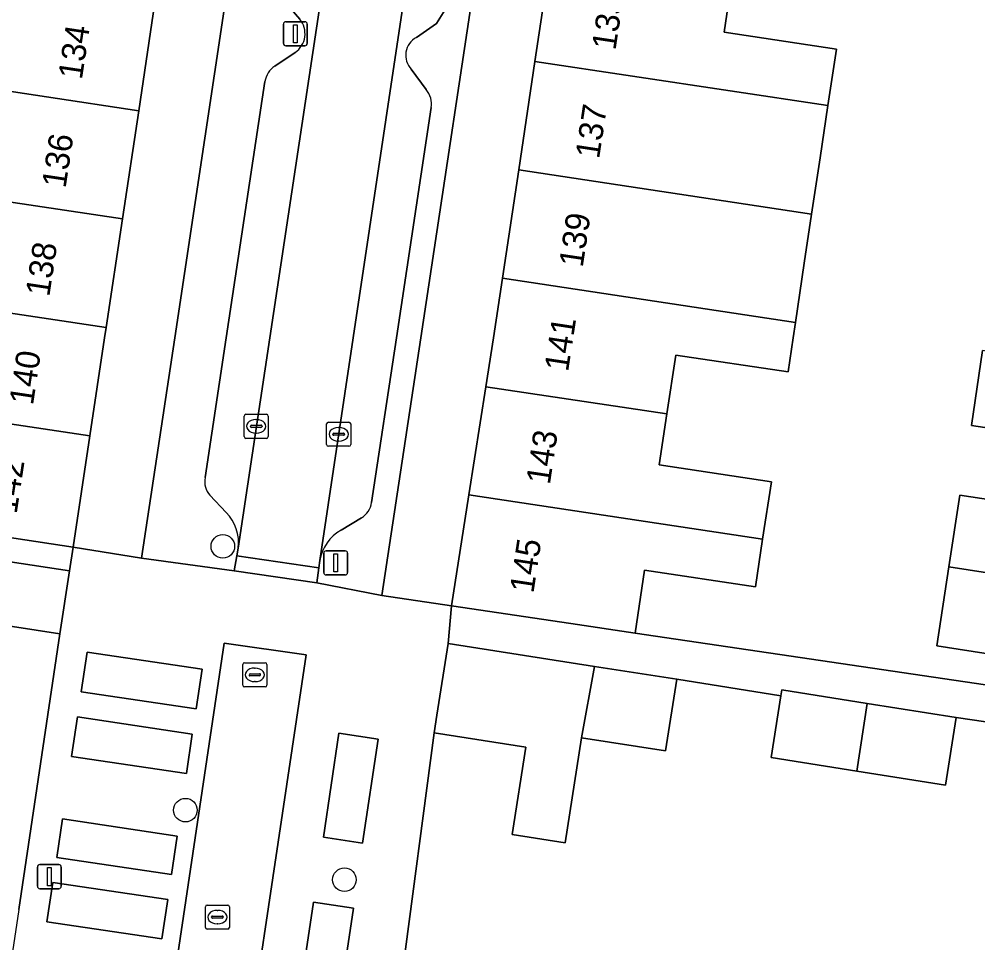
# Model space of a CAD drawing. Extents: x 163008 to 163854, y 382777 to 383982.
# Drawn here: x 163667.4 to 163707.17, y 383224.9 to 383263.21 of the extents above; entities that cross this region are included whole.
import ezdxf

# ---------------------------------------------------------------- set-up
doc = ezdxf.new("R2010")
doc.units = 0
for name, color, linetype in [('IMGEO_Boom', 7, 'Continuous'), ('IMGEO_Erf', 7, 'Continuous'), ('IMGEO_Kolk', 7, 'Continuous'), ('IMGEO_Lichtmast', 7, 'Continuous'), ('IMGEO_Muur', 7, 'Continuous'), ('IMGEO_Pand', 7, 'Continuous'), ('IMGEO_Pand_nummerreeks', 7, 'Continuous'), ('IMGEO_Parkeervlak_open', 7, 'Continuous'), ('IMGEO_Rijbaan_lokaal_open', 7, 'Continuous'), ('IMGEO_Voetpad_open', 7, 'Continuous')]:
    doc.layers.add(name, color=color, linetype=linetype)

msp = doc.modelspace()

# ---------------------------------------------------------------- linework, layer by layer
at = {"layer": 'IMGEO_Boom'}
for centre in [(163675.846, 383241.347), (163674.295, 383230.407), (163680.89, 383227.521)]:
    msp.add_circle(centre, 0.489, dxfattribs=at)
at = {"layer": 'IMGEO_Erf'}
for points in [[(163700.353, 383357.923), (163684.056, 383250), (163682.442, 383239.311), (163685.338, 383238.887), (163686.056, 383243.479), (163686.758, 383247.971), (163687.075, 383250), (163687.445, 383252.466), (163688.119, 383256.962), (163688.794, 383261.46), (163689.468, 383265.956)], [(163696.965, 383264.827), (163696.642, 383262.673), (163701.299, 383261.975), (163700.947, 383259.629), (163700.622, 383257.464), (163700.269, 383255.132), (163699.96, 383253.09), (163699.602, 383250.634), (163699.51, 383250), (163699.303, 383248.58), (163694.635, 383249.284), (163694.266, 383246.84), (163693.948, 383244.73), (163698.601, 383244.029), (163698.241, 383241.643), (163697.943, 383239.667), (163693.341, 383240.361), (163692.947, 383237.75), (163708.335, 383235.474)], [(163709.865, 383245.92), (163706.9, 383246.354), (163707.355, 383249.466)], [(163707.855, 383236.849), (163705.463, 383237.215), (163705.963, 383240.493), (163706.417, 383243.469), (163709.342, 383243.022)], [(163667.379, 383226.279), (163669.088, 383237.721), (163664.162, 383238.475)], [(163710.424, 383233.636), (163706.268, 383234.245), (163705.824, 383231.443), (163702.144, 383232.027), (163698.593, 383232.59), (163699, 383235.152), (163694.675, 383235.839), (163694.21, 383232.86), (163690.723, 383233.405), (163690.042, 383229.054), (163687.848, 383229.397), (163688.413, 383233.024), (163684.611, 383233.617), (163683.271, 383223.496)]]:
    msp.add_lwpolyline(points, dxfattribs=at)
msp.add_lwpolyline([(163681.279, 383299.422), (163678.43, 383299.85), (163677.757, 383295.368), (163677.082, 383290.874), (163676.407, 383286.381), (163675.732, 383281.887), (163675.057, 383277.393), (163674.382, 383272.9), (163673.707, 383268.406), (163673.032, 383263.912), (163672.357, 383259.419), (163671.682, 383254.926), (163671.007, 383250.432), (163670.942, 383250), (163670.331, 383245.933), (163669.638, 383241.316), (163672.477, 383240.858), (163673.851, 383250)], close=True, dxfattribs=at)
at = {"layer": 'IMGEO_Kolk'}
for p, q in [((163676.73, 383245.901), (163676.73, 383246.753)), ((163676.805, 383246.827), (163677.657, 383246.827)), ((163677.731, 383246.753), (163677.731, 383245.901)), ((163677.032, 383246.37), (163677.43, 383246.37)), ((163677.218, 383246.607), (163677.243, 383246.607)), ((163680.152, 383245.571), (163680.152, 383246.423)), ((163680.227, 383246.497), (163681.079, 383246.497)), ((163681.153, 383246.423), (163681.153, 383245.571)), ((163676.989, 383246.321), (163676.989, 383246.333)), ((163677.427, 383246.284), (163677.029, 383246.284)), ((163677.241, 383246.047), (163677.216, 383246.047)), ((163677.473, 383246.333), (163677.473, 383246.321)), ((163680.411, 383245.991), (163680.411, 383246.003)), ((163680.849, 383245.954), (163680.451, 383245.954)), ((163680.454, 383246.04), (163680.852, 383246.04)), ((163680.64, 383246.277), (163680.665, 383246.277)), ((163680.895, 383246.003), (163680.895, 383245.991)), ((163677.657, 383245.827), (163676.805, 383245.827)), ((163680.663, 383245.717), (163680.638, 383245.717)), ((163681.079, 383245.497), (163680.227, 383245.497)), ((163676.673, 383235.592), (163676.673, 383236.444)), ((163676.748, 383236.518), (163677.6, 383236.518)), ((163677.674, 383236.444), (163677.674, 383235.592)), ((163676.932, 383236.012), (163676.932, 383236.024)), ((163676.975, 383236.061), (163677.373, 383236.061)), ((163677.161, 383236.298), (163677.186, 383236.298)), ((163677.416, 383236.024), (163677.416, 383236.012)), ((163677.37, 383235.975), (163676.972, 383235.975)), ((163677.184, 383235.738), (163677.159, 383235.738)), ((163677.6, 383235.518), (163676.748, 383235.518)), ((163675.196, 383226.47), (163676.048, 383226.47)), ((163675.121, 383225.544), (163675.121, 383226.396)), ((163675.609, 383226.25), (163675.634, 383226.25)), ((163676.122, 383226.396), (163676.122, 383225.544)), ((163675.38, 383225.964), (163675.38, 383225.976)), ((163675.818, 383225.927), (163675.42, 383225.927)), ((163675.423, 383226.013), (163675.821, 383226.013)), ((163675.632, 383225.69), (163675.607, 383225.69)), ((163675.864, 383225.976), (163675.864, 383225.964)), ((163676.048, 383225.47), (163675.196, 383225.47))]:
    msp.add_line(p, q, dxfattribs=at)
for points in [[(163676.73, 383245.901), (163676.73, 383246.753)], [(163676.805, 383246.827), (163677.657, 383246.827)], [(163677.731, 383246.753), (163677.731, 383245.901)], [(163680.152, 383245.571), (163680.152, 383246.423)], [(163680.227, 383246.497), (163681.079, 383246.497)], [(163681.153, 383246.423), (163681.153, 383245.571)], [(163677.657, 383245.827), (163676.805, 383245.827)], [(163681.079, 383245.497), (163680.227, 383245.497)], [(163676.673, 383235.592), (163676.673, 383236.444)], [(163676.748, 383236.518), (163677.6, 383236.518)], [(163677.674, 383236.444), (163677.674, 383235.592)], [(163677.6, 383235.518), (163676.748, 383235.518)], [(163675.196, 383226.47), (163676.048, 383226.47)], [(163675.121, 383225.544), (163675.121, 383226.396)], [(163676.122, 383226.396), (163676.122, 383225.544)], [(163676.048, 383225.47), (163675.196, 383225.47)]]:
    msp.add_lwpolyline(points, dxfattribs=at)
for centre, radius, start, end in [((163676.807, 383246.751), 0.0765, 91.552, 178.448), ((163676.807, 383246.751), 0.0765, 91.552, 178.448), ((163677.655, 383246.751), 0.0765, 1.552, 88.448), ((163677.655, 383246.751), 0.0765, 1.552, 88.448), ((163677.029, 383246.33), 0.0403, 85.8775, 175.7526), ((163677.434, 383246.332), 0.0386, 1.7309, 96.639), ((163680.229, 383246.421), 0.0765, 91.552, 178.448), ((163680.229, 383246.421), 0.0765, 91.552, 178.448), ((163681.077, 383246.421), 0.0765, 1.552, 88.448), ((163681.077, 383246.421), 0.0765, 1.552, 88.448), ((163677.026, 383246.32), 0.0366, 178.938, 274.7102), ((163677.43, 383246.327), 0.043, 264.8664, 352.4533), ((163680.451, 383246), 0.0403, 85.8775, 175.7526), ((163680.448, 383245.99), 0.0366, 178.938, 274.7102), ((163680.852, 383245.997), 0.043, 264.8664, 352.4533), ((163680.856, 383246.002), 0.0386, 1.7309, 96.639), ((163676.807, 383245.903), 0.0765, 181.552, 268.448), ((163676.807, 383245.903), 0.0765, 181.552, 268.448), ((163677.655, 383245.903), 0.0765, 271.552, 358.448), ((163677.655, 383245.903), 0.0765, 271.552, 358.448), ((163680.229, 383245.573), 0.0765, 181.552, 268.448), ((163680.229, 383245.573), 0.0765, 181.552, 268.448), ((163681.077, 383245.573), 0.0765, 271.552, 358.448), ((163681.077, 383245.573), 0.0765, 271.552, 358.448), ((163676.75, 383236.442), 0.0765, 91.552, 178.448), ((163676.75, 383236.442), 0.0765, 91.552, 178.448), ((163677.598, 383236.442), 0.0765, 1.552, 88.448), ((163677.598, 383236.442), 0.0765, 1.552, 88.448), ((163676.972, 383236.021), 0.0403, 85.8775, 175.7526), ((163676.969, 383236.011), 0.0366, 178.938, 274.7102), ((163677.373, 383236.018), 0.043, 264.8664, 352.4533), ((163677.377, 383236.023), 0.0386, 1.7309, 96.639), ((163676.75, 383235.594), 0.0765, 181.552, 268.448), ((163676.75, 383235.594), 0.0765, 181.552, 268.448), ((163677.598, 383235.594), 0.0765, 271.552, 358.448), ((163677.598, 383235.594), 0.0765, 271.552, 358.448), ((163675.198, 383226.394), 0.0765, 91.552, 178.448), ((163675.198, 383226.394), 0.0765, 91.552, 178.448), ((163676.046, 383226.394), 0.0765, 1.552, 88.448), ((163676.046, 383226.394), 0.0765, 1.552, 88.448), ((163675.42, 383225.973), 0.0403, 85.8775, 175.7526), ((163675.417, 383225.963), 0.0366, 178.938, 274.7102), ((163675.821, 383225.97), 0.043, 264.8664, 352.4533), ((163675.825, 383225.975), 0.0386, 1.7309, 96.639), ((163675.198, 383225.546), 0.0765, 181.552, 268.448), ((163675.198, 383225.546), 0.0765, 181.552, 268.448), ((163676.046, 383225.546), 0.0765, 271.552, 358.448), ((163676.046, 383225.546), 0.0765, 271.552, 358.448)]:
    msp.add_arc(centre, radius, start, end, dxfattribs=at)
for centre, major_axis, ratio, start_param, end_param in [((163677.217, 383246.327), (-0.387, 0.002), 0.722429, 4.712389, 7.853982), ((163677.242, 383246.327), (-0.39, 0.002), 0.717154, 1.570796, 4.712389), ((163680.639, 383245.997), (-0.387, 0.002), 0.722429, 4.712389, 7.853982), ((163680.664, 383245.997), (-0.39, 0.002), 0.717154, 1.570796, 4.712389), ((163677.16, 383236.018), (-0.387, 0.002), 0.722429, 4.712389, 7.853982), ((163677.185, 383236.018), (-0.39, 0.002), 0.717154, 1.570796, 4.712389), ((163675.608, 383225.97), (-0.387, 0.002), 0.722429, 4.712389, 7.853982), ((163675.633, 383225.97), (-0.39, 0.002), 0.717154, 1.570796, 4.712389)]:
    msp.add_ellipse(centre, major_axis=major_axis, ratio=ratio, start_param=start_param, end_param=end_param, dxfattribs=at)
at = {"layer": 'IMGEO_Lichtmast'}
for p, q in [((163678.459, 383263.11), (163679.249, 383263.11)), ((163679.249, 383263.11), (163678.459, 383263.11)), ((163678.359, 383262.21), (163678.359, 383263.01)), ((163678.359, 383263.01), (163678.359, 383262.21)), ((163679.349, 383263.01), (163679.349, 383262.21)), ((163679.349, 383262.21), (163679.349, 383263.01)), ((163679.249, 383262.11), (163678.459, 383262.11)), ((163678.459, 383262.11), (163679.249, 383262.11)), ((163680.032, 383240.261), (163680.032, 383241.061)), ((163680.032, 383241.061), (163680.032, 383240.261)), ((163680.132, 383241.161), (163680.922, 383241.161)), ((163680.922, 383241.161), (163680.132, 383241.161)), ((163681.022, 383241.061), (163681.022, 383240.261)), ((163681.022, 383240.261), (163681.022, 383241.061)), ((163680.922, 383240.161), (163680.132, 383240.161)), ((163680.132, 383240.161), (163680.922, 383240.161)), ((163668.251, 383228.148), (163669.041, 383228.148)), ((163669.041, 383228.148), (163668.251, 383228.148)), ((163668.151, 383227.248), (163668.151, 383228.048)), ((163668.151, 383228.048), (163668.151, 383227.248)), ((163669.141, 383228.048), (163669.141, 383227.248)), ((163669.141, 383227.248), (163669.141, 383228.048)), ((163669.041, 383227.148), (163668.251, 383227.148)), ((163668.251, 383227.148), (163669.041, 383227.148))]:
    msp.add_line(p, q, dxfattribs=at)
for points in [[(163678.779, 383262.985), (163678.929, 383262.985), (163678.929, 383262.235), (163678.779, 383262.235), (163678.779, 383262.985)], [(163680.452, 383241.036), (163680.602, 383241.036), (163680.602, 383240.286), (163680.452, 383240.286), (163680.452, 383241.036)], [(163668.571, 383228.023), (163668.721, 383228.023), (163668.721, 383227.273), (163668.571, 383227.273), (163668.571, 383228.023)]]:
    msp.add_lwpolyline(points, dxfattribs=at)
for centre, start, end in [((163678.459, 383263.01), 90, 180), ((163678.459, 383263.01), 90, 180), ((163679.249, 383263.01), 0, 90), ((163679.249, 383263.01), 360, 90), ((163678.459, 383262.21), 180, 270), ((163678.459, 383262.21), 180, 270), ((163679.249, 383262.21), 270, 0), ((163679.249, 383262.21), 270, 0), ((163680.132, 383241.061), 90, 180), ((163680.132, 383241.061), 90, 180), ((163680.922, 383241.061), 0, 90), ((163680.922, 383241.061), 360, 90), ((163680.132, 383240.261), 180, 270), ((163680.132, 383240.261), 180, 270), ((163680.922, 383240.261), 270, 0), ((163680.922, 383240.261), 270, 0), ((163668.251, 383228.048), 90, 180), ((163668.251, 383228.048), 90, 180), ((163669.041, 383228.048), 0, 90), ((163669.041, 383228.048), 360, 90), ((163668.251, 383227.248), 180, 270), ((163668.251, 383227.248), 180, 270), ((163669.041, 383227.248), 270, 0), ((163669.041, 383227.248), 270, 0)]:
    msp.add_arc(centre, 0.1, start, end, dxfattribs=at)
at = {"layer": 'IMGEO_Muur'}
for points in [[(163667.379, 383226.279), (163669.088, 383237.721)], [(163684.611, 383233.617), (163683.271, 383223.496)]]:
    msp.add_lwpolyline(points, dxfattribs=at)
at = {"layer": 'IMGEO_Pand'}
for points in [[(163688.794, 383261.46), (163700.947, 383259.629), (163701.299, 383261.975), (163696.642, 383262.673), (163696.965, 383264.827), (163689.468, 383265.956)], [(163672.357, 383259.419), (163673.032, 383263.912), (163660.745, 383265.752), (163660.398, 383263.44), (163665.012, 383262.748), (163664.685, 383260.568)], [(163688.794, 383261.46), (163688.119, 383256.962), (163700.269, 383255.132), (163700.622, 383257.464), (163700.947, 383259.629)], [(163664.685, 383260.568), (163664.346, 383258.307), (163659.698, 383259.004), (163659.363, 383256.77), (163671.682, 383254.926), (163672.357, 383259.419)], [(163671.682, 383254.926), (163659.363, 383256.77), (163659.002, 383254.363), (163658.729, 383252.27), (163660.32, 383252.032), (163671.007, 383250.432)], [(163687.445, 383252.466), (163699.602, 383250.634), (163699.96, 383253.09), (163700.269, 383255.132), (163688.119, 383256.962)], [(163687.445, 383252.466), (163687.075, 383250), (163686.758, 383247.971), (163694.266, 383246.84), (163694.635, 383249.284), (163699.303, 383248.58), (163699.51, 383250), (163699.602, 383250.634)], [(163670.942, 383250), (163671.007, 383250.432), (163660.32, 383252.032), (163658.729, 383252.27), (163658.388, 383250), (163658.054, 383247.777), (163670.331, 383245.933)], [(163710.319, 383249.019), (163707.355, 383249.466), (163706.9, 383246.354), (163709.865, 383245.92)], [(163686.758, 383247.971), (163686.056, 383243.479), (163698.241, 383241.643), (163698.601, 383244.029), (163693.948, 383244.73), (163694.266, 383246.84)], [(163670.331, 383245.933), (163658.054, 383247.777), (163657.732, 383245.634), (163662.617, 383244.901), (163662.245, 383242.425), (163664.694, 383242.058), (163669.638, 383241.316)], [(163686.056, 383243.479), (163685.338, 383238.887), (163690.284, 383238.148), (163692.947, 383237.75), (163693.341, 383240.361), (163697.943, 383239.667), (163698.241, 383241.643)], [(163709.558, 383242.989), (163709.515, 383242.996), (163709.443, 383243.007), (163709.342, 383243.022), (163706.417, 383243.469), (163705.963, 383240.493), (163708.187, 383240.158), (163708.889, 383240.052), (163709.105, 383240.019)], [(163664.162, 383238.475), (163669.088, 383237.721), (163669.487, 383240.33), (163664.555, 383241.085)], [(163709.105, 383240.019), (163708.889, 383240.052), (163708.187, 383240.158), (163705.963, 383240.493), (163705.463, 383237.215), (163707.855, 383236.849), (163708.388, 383236.768), (163708.532, 383236.746), (163708.604, 383236.735)], [(163691.269, 383236.371), (163685.19, 383237.321), (163684.724, 383234.342), (163684.611, 383233.617), (163688.413, 383233.024), (163687.848, 383229.397), (163690.042, 383229.054), (163690.723, 383233.405)], [(163691.269, 383236.371), (163690.723, 383233.405), (163694.21, 383232.86), (163694.675, 383235.839)], [(163702.577, 383234.831), (163699.038, 383235.393), (163699, 383235.152), (163698.593, 383232.59), (163702.144, 383232.027)], [(163702.577, 383234.831), (163702.144, 383232.027), (163705.824, 383231.443), (163706.268, 383234.245)]]:
    msp.add_lwpolyline(points, close=True, dxfattribs=at)
at = {"layer": 'IMGEO_Parkeervlak_open'}
for points in [[(163676.485, 383241.271), (163677.8, 383250), (163682.735, 383282.763), (163683.352, 383286.868)], [(163686.716, 383286.461), (163681.251, 383250), (163679.869, 383240.759)], [(163683.875, 383262.459), (163684.706, 383263.035), (163685.126, 383263.702), (163688.142, 383283.47)], [(163678.422, 383263.937), (163679.041, 383263.214)], [(163678.847, 383261.835), (163678.002, 383261.27)], [(163684.279, 383260.295), (163683.662, 383261.136)], [(163677.595, 383260.623), (163675.989, 383250), (163675.111, 383244.197)], [(163682.013, 383243.165), (163683.049, 383250), (163684.495, 383259.544)], [(163675.309, 383243.468), (163675.985, 383242.754)], [(163680.75, 383242.02), (163681.597, 383242.531)]]:
    msp.add_lwpolyline(points, dxfattribs=at)
for points in [[(163674.743, 383234.609), (163674.987, 383236.25), (163670.216, 383236.96), (163669.972, 383235.319)], [(163674.337, 383231.921), (163674.581, 383233.563), (163669.816, 383234.272), (163669.572, 383232.63)], [(163681.644, 383229.04), (163682.287, 383233.356), (163680.665, 383233.597), (163680.022, 383229.281)], [(163673.713, 383227.74), (163673.949, 383229.331), (163669.191, 383230.039), (163668.955, 383228.448)], [(163673.32, 383225.068), (163673.563, 383226.697), (163668.789, 383227.408), (163668.546, 383225.779)], [(163680.623, 383222), (163681.269, 383226.341), (163679.601, 383226.589), (163678.955, 383222.248)]]:
    msp.add_lwpolyline(points, close=True, dxfattribs=at)
for centre, radius, start, end in [((163678.314, 383262.613), 0.943, 304.4119, 39.5723), ((163684.28, 383261.715), 0.847, 118.5877, 223.1203), ((163678.554, 383260.471), 0.971, 124.6464, 171.0091), ((163683.621, 383259.699), 0.887, 349.9198, 42.1724), ((163675.96, 383244.036), 0.864, 169.2642, 221.1263), ((163681.154, 383243.275), 0.866, 300.7767, 352.6814), ((163674.703, 383241.496), 1.796, 352.7981, 44.4655), ((163681.664, 383240.443), 1.823, 120.105, 170.0147)]:
    msp.add_arc(centre, radius, start, end, dxfattribs=at)
at = {"layer": 'IMGEO_Rijbaan_lokaal_open'}
for points in [[(163683.417, 383287.32), (163683.352, 383286.868), (163682.735, 383282.763), (163677.8, 383250), (163676.485, 383241.271), (163676.429, 383240.958), (163679.828, 383240.462), (163679.869, 383240.759), (163681.251, 383250), (163686.716, 383286.461), (163686.772, 383286.817)], [(163676.429, 383240.958), (163676.315, 383240.328), (163679.739, 383239.828), (163679.828, 383240.462)], [(163675.78, 383213.262), (163679.31, 383236.852), (163675.895, 383237.339), (163672.384, 383213.757)]]:
    msp.add_lwpolyline(points, close=True, dxfattribs=at)
at = {"layer": 'IMGEO_Voetpad_open'}
for points in [[(163693.969, 383357.75), (163694.031, 383358.138), (163694.133, 383358.769), (163690.288, 383359.355), (163681.486, 383300.797), (163681.279, 383299.422), (163673.851, 383250), (163672.477, 383240.858), (163676.315, 383240.328), (163676.429, 383240.958), (163676.485, 383241.271)], [(163679.869, 383240.759), (163679.828, 383240.462), (163679.739, 383239.828), (163682.442, 383239.311), (163684.056, 383250), (163700.353, 383357.923)], [(163688.142, 383283.47), (163685.126, 383263.702), (163684.706, 383263.035), (163683.875, 383262.459)], [(163679.041, 383263.214), (163678.422, 383263.937)], [(163678.002, 383261.27), (163678.847, 383261.835)], [(163683.662, 383261.136), (163684.279, 383260.295)], [(163675.111, 383244.197), (163675.989, 383250), (163677.595, 383260.623)], [(163684.495, 383259.544), (163683.049, 383250), (163682.013, 383243.165)], [(163675.985, 383242.754), (163675.309, 383243.468)], [(163681.597, 383242.531), (163680.75, 383242.02)], [(163664.555, 383241.085), (163669.487, 383240.33), (163669.638, 383241.316), (163664.694, 383242.058)], [(163708.335, 383235.474), (163692.947, 383237.75), (163690.284, 383238.148), (163685.338, 383238.887), (163685.19, 383237.321), (163691.269, 383236.371), (163694.675, 383235.839), (163699, 383235.152), (163699.038, 383235.393), (163702.577, 383234.831), (163706.268, 383234.245), (163710.424, 383233.636)]]:
    msp.add_lwpolyline(points, dxfattribs=at)
for points in [[(163685.19, 383237.321), (163685.338, 383238.887), (163682.442, 383239.311), (163679.739, 383239.828), (163676.315, 383240.328), (163672.477, 383240.858), (163669.638, 383241.316), (163669.487, 383240.33), (163669.088, 383237.721), (163667.379, 383226.279), (163666.2, 383218.445), (163665.554, 383214.294), (163672.384, 383213.757), (163675.895, 383237.339), (163679.31, 383236.852), (163675.78, 383213.262), (163681.523, 383212.114), (163682.127, 383216.078), (163683.271, 383223.496), (163684.611, 383233.617), (163684.724, 383234.342)], [(163674.743, 383234.609), (163669.972, 383235.319), (163670.216, 383236.96), (163674.987, 383236.25)], [(163674.337, 383231.921), (163669.572, 383232.63), (163669.816, 383234.272), (163674.581, 383233.563)], [(163682.287, 383233.356), (163681.644, 383229.04), (163680.022, 383229.281), (163680.665, 383233.597)], [(163673.713, 383227.74), (163668.955, 383228.448), (163669.191, 383230.039), (163673.949, 383229.331)], [(163673.32, 383225.068), (163668.546, 383225.779), (163668.789, 383227.408), (163673.563, 383226.697)], [(163681.269, 383226.341), (163680.623, 383222), (163678.955, 383222.248), (163679.601, 383226.589)]]:
    msp.add_lwpolyline(points, close=True, dxfattribs=at)
for centre, radius, start, end in [((163678.314, 383262.613), 0.943, 304.4119, 39.5723), ((163684.28, 383261.715), 0.847, 118.5877, 223.1203), ((163678.554, 383260.471), 0.971, 124.6464, 171.0091), ((163683.621, 383259.699), 0.887, 349.9198, 42.1724), ((163675.96, 383244.036), 0.864, 169.2642, 221.1263), ((163681.154, 383243.275), 0.866, 300.7767, 352.6814), ((163674.703, 383241.496), 1.796, 352.7981, 44.4655), ((163681.664, 383240.443), 1.823, 120.105, 170.0147)]:
    msp.add_arc(centre, radius, start, end, dxfattribs=at)

# ---------------------------------------------------------------- texts
at = {"layer": 'IMGEO_Pand_nummerreeks'}
for s, rotation, p in [('135', 81.4036, (163692.134, 383261.897)), ('134', 81.4578, (163669.999, 383260.68)), ('137', 81.4036, (163691.454, 383257.393)), ('136', 81.4578, (163669.322, 383256.177)), ('139', 81.4036, (163690.773, 383252.889)), ('138', 81.4574, (163668.646, 383251.678)), ('141', 81.3104, (163690.168, 383248.564)), ('140', 81.4574, (163667.97, 383247.176)), ('143', 81.4036, (163689.411, 383243.88)), ('142', 81.4578, (163667.292, 383242.667)), ('145', 81.4036, (163688.73, 383239.376))]:
    msp.add_text(s, height=1, rotation=rotation, dxfattribs=at).set_placement(p)

doc.saveas('drawing.dxf')
